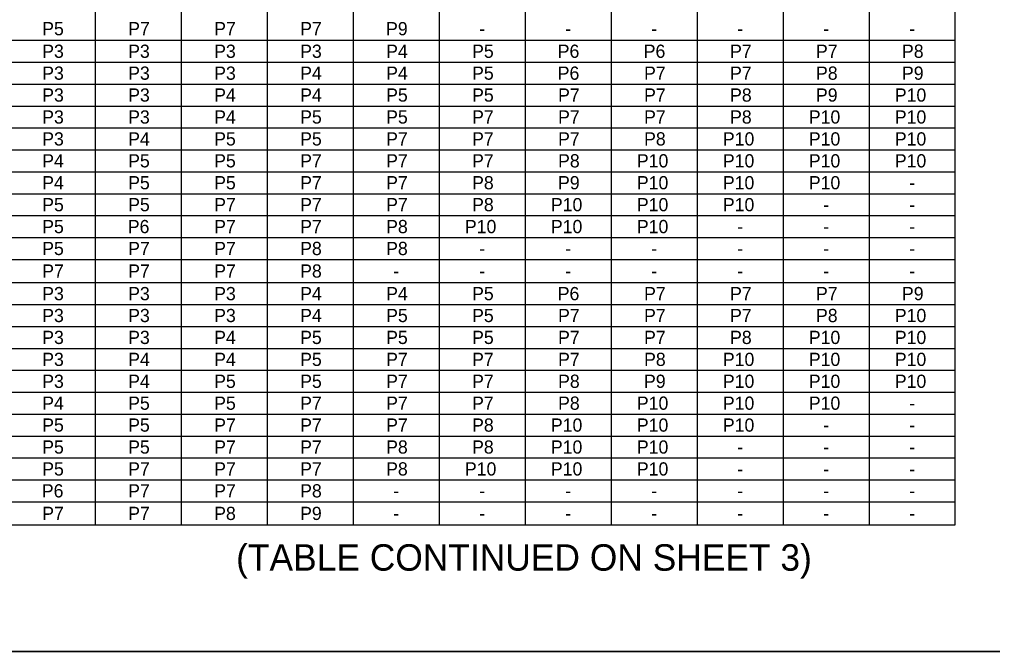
# Model space of a CAD drawing. Extents: x 637580 to 641008, y 294594 to 295782.
# Drawn here: x 638664.4 to 638885.2, y 295202.6 to 295346 of the extents above; entities that cross this region are included whole.
import ezdxf

# ---------------------------------------------------------------- set-up
doc = ezdxf.new("R2010")
doc.units = 0
for name, color, linetype in [('1', 7, 'Continuous'), ('2', 7, 'Continuous'), ('3', 7, 'Continuous')]:
    doc.layers.add(name, color=color, linetype=linetype)

msp = doc.modelspace()

# ---------------------------------------------------------------- linework, layer by layer
at = {"layer": '1'}
for p, q in [((638876.73, 295231.34), (638876.73, 295750.63)), ((638681.66, 295231.34), (638681.66, 295735.61)), ((638701.17, 295231.34), (638701.17, 295735.61)), ((638720.67, 295231.34), (638720.67, 295735.61)), ((638740.18, 295231.34), (638740.18, 295735.61)), ((638759.69, 295231.34), (638759.69, 295735.61)), ((638779.2, 295231.34), (638779.2, 295735.61)), ((638798.7, 295231.34), (638798.7, 295735.61)), ((638818.21, 295231.34), (638818.21, 295735.61)), ((638837.72, 295231.34), (638837.72, 295735.61)), ((638857.23, 295231.34), (638857.23, 295735.61)), ((638509.81, 295341.32), (638876.73, 295341.32)), ((638509.81, 295286.33), (638876.73, 295286.33)), ((638509.81, 295231.34), (638876.73, 295231.34)), ((639247.31, 295202.63), (638461.31, 295202.63)), ((638461.31, 295202.63), (639047.31, 295202.63))]:
    msp.add_line(p, q, dxfattribs=at)
at = {"layer": '2'}
for p, q in [((638536.61, 295336.35), (638876.73, 295336.35)), ((638536.61, 295331.37), (638876.73, 295331.37)), ((638536.61, 295326.4), (638876.73, 295326.4)), ((638536.61, 295321.43), (638876.73, 295321.43)), ((638536.61, 295316.46), (638876.73, 295316.46)), ((638536.61, 295311.48), (638876.73, 295311.48)), ((638536.61, 295306.51), (638876.73, 295306.51)), ((638536.61, 295301.54), (638876.73, 295301.54)), ((638536.61, 295296.57), (638876.73, 295296.57)), ((638536.61, 295291.59), (638876.73, 295291.59)), ((638536.61, 295281.36), (638876.73, 295281.36)), ((638536.61, 295276.38), (638876.73, 295276.38)), ((638536.61, 295271.41), (638876.73, 295271.41)), ((638536.61, 295266.44), (638876.73, 295266.44)), ((638536.61, 295261.47), (638876.73, 295261.47)), ((638536.61, 295256.49), (638876.73, 295256.49)), ((638536.61, 295251.52), (638876.73, 295251.52)), ((638536.61, 295246.55), (638876.73, 295246.55)), ((638536.61, 295241.58), (638876.73, 295241.58)), ((638536.61, 295236.6), (638876.73, 295236.6))]:
    msp.add_line(p, q, dxfattribs=at)

# ---------------------------------------------------------------- texts
at = {"layer": '1'}
for s, p in [('P5', (638669.56, 295342.45)), ('P7', (638689.06, 295342.45)), ('P7', (638708.57, 295342.45)), ('P7', (638728.08, 295342.45)), ('P9', (638747.57, 295342.45)), ('-', (638768.71, 295342.45)), ('-', (638788.22, 295342.45)), ('-', (638807.73, 295342.45)), ('-', (638827.23, 295342.45)), ('-', (638846.74, 295342.45)), ('-', (638866.25, 295342.45)), ('P3', (638669.56, 295337.33)), ('P3', (638689.06, 295337.33)), ('P3', (638708.57, 295337.33)), ('P3', (638728.08, 295337.33)), ('P4', (638747.59, 295337.33)), ('P5', (638767.09, 295337.33)), ('P6', (638786.52, 295337.33)), ('P6', (638806.03, 295337.33)), ('P7', (638825.62, 295337.33)), ('P7', (638845.12, 295337.33)), ('P8', (638864.63, 295337.33)), ('P3', (638669.56, 295332.36)), ('P3', (638689.06, 295332.36)), ('P3', (638708.57, 295332.36)), ('P4', (638728.08, 295332.36)), ('P4', (638747.59, 295332.36)), ('P5', (638767.09, 295332.36)), ('P6', (638786.52, 295332.36)), ('P7', (638806.11, 295332.36)), ('P7', (638825.62, 295332.36)), ('P8', (638845.12, 295332.36)), ('P9', (638864.62, 295332.36)), ('P3', (638669.56, 295327.39)), ('P3', (638689.06, 295327.39)), ('P4', (638708.57, 295327.39)), ('P4', (638728.08, 295327.39)), ('P5', (638747.59, 295327.39)), ('P5', (638767.09, 295327.39)), ('P7', (638786.6, 295327.39)), ('P7', (638806.11, 295327.39)), ('P8', (638825.62, 295327.39)), ('P9', (638845.11, 295327.39)), ('P10', (638863, 295327.39)), ('P3', (638669.56, 295322.41)), ('P3', (638689.06, 295322.41)), ('P4', (638708.57, 295322.41)), ('P5', (638728.08, 295322.41)), ('P5', (638747.59, 295322.41)), ('P7', (638767.09, 295322.41)), ('P7', (638786.6, 295322.41)), ('P7', (638806.11, 295322.41)), ('P8', (638825.62, 295322.41)), ('P10', (638843.49, 295322.41)), ('P10', (638863, 295322.41)), ('P3', (638669.56, 295317.44)), ('P4', (638689.06, 295317.44)), ('P5', (638708.57, 295317.44)), ('P5', (638728.08, 295317.44)), ('P7', (638747.59, 295317.44)), ('P7', (638767.09, 295317.44)), ('P7', (638786.6, 295317.44)), ('P8', (638806.11, 295317.44)), ('P10', (638823.99, 295317.44)), ('P10', (638843.49, 295317.44)), ('P10', (638863, 295317.44)), ('P4', (638669.56, 295312.47)), ('P5', (638689.06, 295312.47)), ('P5', (638708.57, 295312.47)), ('P7', (638728.08, 295312.47)), ('P7', (638747.59, 295312.47)), ('P7', (638767.09, 295312.47)), ('P8', (638786.6, 295312.47)), ('P10', (638804.48, 295312.47)), ('P10', (638823.99, 295312.47)), ('P10', (638843.49, 295312.47)), ('P10', (638863, 295312.47)), ('P4', (638669.56, 295307.5)), ('P5', (638689.06, 295307.5)), ('P5', (638708.57, 295307.5)), ('P7', (638728.08, 295307.5)), ('P7', (638747.59, 295307.5)), ('P8', (638767.09, 295307.5)), ('P9', (638786.59, 295307.5)), ('P10', (638804.48, 295307.5)), ('P10', (638823.99, 295307.5)), ('P10', (638843.49, 295307.5)), ('-', (638866.25, 295307.5)), ('P5', (638669.56, 295302.52)), ('P5', (638689.06, 295302.52)), ('P7', (638708.57, 295302.52)), ('P7', (638728.08, 295302.52)), ('P7', (638747.59, 295302.52)), ('P8', (638767.09, 295302.52)), ('P10', (638784.97, 295302.52)), ('P10', (638804.48, 295302.52)), ('P10', (638823.99, 295302.52)), ('-', (638846.74, 295302.52)), ('-', (638866.25, 295302.52)), ('P6', (638688.98, 295297.55)), ('P8', (638747.59, 295297.55)), ('P10', (638765.46, 295297.55)), ('P10', (638784.97, 295297.55)), ('P10', (638804.48, 295297.55)), ('P5', (638669.56, 295297.55)), ('P7', (638708.57, 295297.55)), ('P7', (638728.08, 295297.55)), ('-', (638827.23, 295297.55)), ('-', (638846.74, 295297.55)), ('-', (638866.25, 295297.55)), ('P5', (638669.56, 295292.58)), ('P7', (638689.06, 295292.58)), ('P7', (638708.57, 295292.58)), ('P8', (638728.08, 295292.58)), ('P8', (638747.59, 295292.58)), ('-', (638768.71, 295292.58)), ('-', (638788.22, 295292.58)), ('-', (638807.73, 295292.58)), ('-', (638827.23, 295292.58)), ('-', (638846.74, 295292.58)), ('-', (638866.25, 295292.58)), ('P7', (638669.56, 295287.46)), ('P7', (638689.06, 295287.46)), ('P7', (638708.57, 295287.46)), ('P8', (638728.08, 295287.46)), ('-', (638749.2, 295287.46)), ('-', (638768.71, 295287.46)), ('-', (638788.22, 295287.46)), ('-', (638807.73, 295287.46)), ('-', (638827.23, 295287.46)), ('-', (638846.74, 295287.46)), ('-', (638866.25, 295287.46)), ('P3', (638669.56, 295282.34)), ('P3', (638689.06, 295282.34)), ('P3', (638708.57, 295282.34)), ('P4', (638728.08, 295282.34)), ('P4', (638747.59, 295282.34)), ('P5', (638767.09, 295282.34)), ('P6', (638786.52, 295282.34)), ('P7', (638806.11, 295282.34)), ('P7', (638825.62, 295282.34)), ('P7', (638845.12, 295282.34)), ('P9', (638864.62, 295282.34)), ('P3', (638669.56, 295277.37)), ('P3', (638689.06, 295277.37)), ('P3', (638708.57, 295277.37)), ('P4', (638728.08, 295277.37)), ('P5', (638747.59, 295277.37)), ('P5', (638767.09, 295277.37)), ('P7', (638786.6, 295277.37)), ('P7', (638806.11, 295277.37)), ('P7', (638825.62, 295277.37)), ('P8', (638845.12, 295277.37)), ('P10', (638863, 295277.37)), ('P3', (638669.56, 295272.4)), ('P3', (638689.06, 295272.4)), ('P4', (638708.57, 295272.4)), ('P5', (638728.08, 295272.4)), ('P5', (638747.59, 295272.4)), ('P5', (638767.09, 295272.4)), ('P7', (638786.6, 295272.4)), ('P7', (638806.11, 295272.4)), ('P8', (638825.62, 295272.4)), ('P10', (638843.49, 295272.4)), ('P10', (638863, 295272.4)), ('P3', (638669.56, 295267.42)), ('P4', (638689.06, 295267.42)), ('P4', (638708.57, 295267.42)), ('P5', (638728.08, 295267.42)), ('P7', (638747.59, 295267.42)), ('P7', (638767.09, 295267.42)), ('P7', (638786.6, 295267.42)), ('P8', (638806.11, 295267.42)), ('P10', (638823.99, 295267.42)), ('P10', (638843.49, 295267.42)), ('P10', (638863, 295267.42)), ('P3', (638669.56, 295262.45)), ('P4', (638689.06, 295262.45)), ('P5', (638708.57, 295262.45)), ('P5', (638728.08, 295262.45)), ('P7', (638747.59, 295262.45)), ('P7', (638767.09, 295262.45)), ('P8', (638786.6, 295262.45)), ('P9', (638806.1, 295262.45)), ('P10', (638823.99, 295262.45)), ('P10', (638843.49, 295262.45)), ('P10', (638863, 295262.45)), ('P4', (638669.56, 295257.48)), ('P5', (638689.06, 295257.48)), ('P5', (638708.57, 295257.48)), ('P7', (638728.08, 295257.48)), ('P7', (638747.59, 295257.48)), ('P7', (638767.09, 295257.48)), ('P8', (638786.6, 295257.48)), ('P10', (638804.48, 295257.48)), ('P10', (638823.99, 295257.48)), ('P10', (638843.49, 295257.48)), ('-', (638866.25, 295257.48)), ('P5', (638669.56, 295252.51)), ('P5', (638689.06, 295252.51)), ('P7', (638708.57, 295252.51)), ('P7', (638728.08, 295252.51)), ('P7', (638747.59, 295252.51)), ('P8', (638767.09, 295252.51)), ('P10', (638784.97, 295252.51)), ('P10', (638804.48, 295252.51)), ('P10', (638823.99, 295252.51)), ('-', (638846.74, 295252.51)), ('-', (638866.25, 295252.51)), ('P5', (638669.56, 295247.53)), ('P5', (638689.06, 295247.53)), ('P7', (638708.57, 295247.53)), ('P7', (638728.08, 295247.53)), ('P8', (638747.59, 295247.53)), ('P8', (638767.09, 295247.53)), ('P10', (638784.97, 295247.53)), ('P10', (638804.48, 295247.53)), ('-', (638827.23, 295247.53)), ('-', (638846.74, 295247.53)), ('-', (638866.25, 295247.53)), ('P5', (638669.56, 295242.56)), ('P7', (638689.06, 295242.56)), ('P7', (638708.57, 295242.56)), ('P7', (638728.08, 295242.56)), ('P8', (638747.59, 295242.56)), ('P10', (638765.46, 295242.56)), ('P10', (638784.97, 295242.56)), ('P10', (638804.48, 295242.56)), ('-', (638827.23, 295242.56)), ('-', (638846.74, 295242.56)), ('-', (638866.25, 295242.56)), ('P6', (638669.47, 295237.59)), ('P7', (638689.06, 295237.59)), ('P7', (638708.57, 295237.59)), ('P8', (638728.08, 295237.59)), ('-', (638749.2, 295237.59)), ('-', (638768.71, 295237.59)), ('-', (638788.22, 295237.59)), ('-', (638807.73, 295237.59)), ('-', (638827.23, 295237.59)), ('-', (638846.74, 295237.59)), ('-', (638866.25, 295237.59)), ('P7', (638669.56, 295232.47)), ('P7', (638689.06, 295232.47)), ('P8', (638708.57, 295232.47)), ('P9', (638728.07, 295232.47)), ('-', (638749.2, 295232.47)), ('-', (638768.71, 295232.47)), ('-', (638788.22, 295232.47)), ('-', (638807.73, 295232.47)), ('-', (638827.23, 295232.47)), ('-', (638846.74, 295232.47)), ('-', (638866.25, 295232.47))]:
    msp.add_text(s, height=3, dxfattribs=at).set_placement(p)
at = {"layer": '3'}
msp.add_text('(TABLE CONTINUED ON SHEET 3)', height=6, dxfattribs=at).set_placement((638713.56, 295220.97))

doc.saveas('drawing.dxf')
